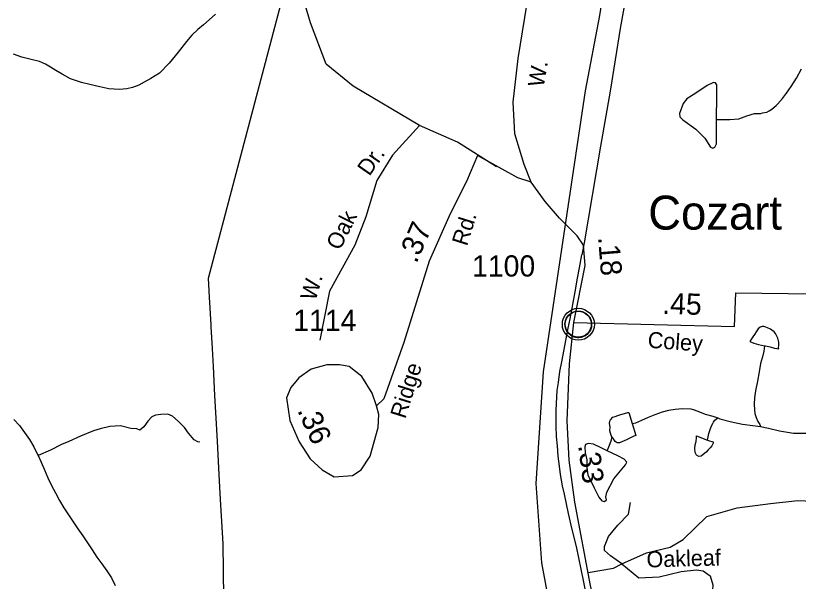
# Model space of a CAD drawing. Extents: x 2056842 to 2160602, y 826753 to 1016856.
# Drawn here: x 2061647 to 2066259, y 853489 to 856821 of the extents above; entities that cross this region are included whole.
import ezdxf

# ---------------------------------------------------------------- set-up
doc = ezdxf.new("R2010")
doc.units = 0
for name, color, linetype in [('Exist Boundary Land Use Reservation Military US Department of Defense', 7, 'Continuous'), ('Exist Boundary Political City Limit New', 7, 'Continuous'), ('Exist Civil Demographics Community CELL', 7, 'Continuous'), ('Exist Civil Demographics Community Label', 7, 'Continuous'), ('Exist Hydrographic Creek Single Shore', 7, 'Continuous'), ('Exist Hydrographic Misc Water Feature', 7, 'Continuous'), ('Exist Railroad Mainline', 7, 'Continuous'), ('Exist Road Non-System Type 51', 7, 'Continuous'), ('Exist Road Non-System Type 51 Label', 7, 'Continuous'), ('Exist Road Secondary Mileage Hundredths English Label', 7, 'Continuous'), ('Exist Road Secondary Type 41 Attributed', 7, 'Continuous'), ('Exist Road Secondary Type 51 Attributed', 7, 'Continuous'), ('Exist Road Secondary Type 51 Label', 7, 'Continuous'), ('Exist Road Secondary Type 51 Number Label', 7, 'Continuous'), ('Map Preparation Boundary City Limit Buffer Line', 7, 'Continuous')]:
    doc.layers.add(name, color=color, linetype=linetype)

msp = doc.modelspace()

# ---------------------------------------------------------------- linework, layer by layer
at = {"layer": 'Exist Boundary Land Use Reservation Military US Department of Defense'}
msp.add_lwpolyline([(2066174.9, 861104.2), (2065853.1, 860720.1), (2065640.8, 860375.6), (2065493.3, 859741.1), (2065336, 858409.3), (2065087.8, 856821.5), (2065002.7, 856377.5), (2064755.9, 854722.1), (2064712.1, 854064.9), (2064745.7, 853597), (2064847.7, 853049), (2064892.2, 852688.1), (2064867, 852393.5), (2064779.9, 852040.8), (2064686.1, 851837.6), (2064419.3, 851474.7), (2064046, 851187.2), (2063767.2, 850891.2), (2063676.8, 850746.1), (2063576.4, 850501.5), (2063457.1, 850039.1), (2063355.1, 849757.2), (2063118.8, 849274.6)], dxfattribs=at)
at = {"layer": 'Exist Boundary Political City Limit New'}
msp.add_lwpolyline([(2062879, 852914.1), (2062869.1, 853709.2), (2062856.4, 853940.2), (2062852.9, 854005.3), (2062844.6, 854155.2), (2062835.9, 854315.1), (2062826.6, 854483.7), (2062821.2, 854582.9), (2062811.9, 854754.9), (2062806, 854860.4), (2062799, 854988.2), (2062798.4, 855000), (2062789.5, 855162.2), (2062783.2, 855275.6), (2063229.1, 856963.7)], dxfattribs=at)
at = {"layer": 'Exist Civil Demographics Community CELL'}
msp.add_lwpolyline([(2064884.9, 855015.5), (2064885.9, 855021.1), (2064887.6, 855027.7), (2064890.6, 855034.9), (2064893.5, 855040.6), (2064896.8, 855046.4), (2064900.6, 855051.5), (2064904.6, 855055.8), (2064909.1, 855060.4), (2064914.7, 855065), (2064920.1, 855068.7), (2064925, 855071.6), (2064930, 855074), (2064935.5, 855076.3), (2064941.1, 855078.1), (2064945.5, 855079.3), (2064950.3, 855080), (2064954.4, 855080.7), (2064960.8, 855081), (2064965.2, 855080.9), (2064970.9, 855080.6), (2064975.8, 855079.9), (2064980.7, 855078.9), (2064985.7, 855077.5), (2064990.9, 855075.6), (2064997.5, 855072.7), (2065003.8, 855069.2), (2065008.9, 855065.6), (2065014, 855061.6), (2065017.3, 855058.5), (2065021.5, 855054.1), (2065025.3, 855049.4), (2065028.4, 855044.8), (2065031.5, 855039.8), (2065034, 855034.6), (2065036, 855029.6), (2065037.6, 855024.6), (2065038.9, 855020), (2065040, 855014), (2065040.6, 855009.3), (2065040.8, 855003.3), (2065040.7, 854997.5), (2065040.1, 854991.8), (2065039.1, 854986.3), (2065037.5, 854980.1), (2065035.6, 854974.3), (2065033.3, 854969.2), (2065030.2, 854963.2), (2065026.9, 854957.9), (2065023.4, 854953.2), (2065019.2, 854948.5), (2065013.9, 854943.5), (2065008.9, 854939.4), (2065003.9, 854935.9), (2064999.6, 854933.4), (2064992.8, 854930.2), (2064985.6, 854927.5), (2064979.7, 854926), (2064973.1, 854924.7), (2064968.6, 854924.3), (2064964.1, 854924), (2064958.6, 854924), (2064954.3, 854924.4), (2064948.6, 854925.1), (2064942.7, 854926.4), (2064938.1, 854927.8), (2064933, 854929.6), (2064928.4, 854931.6), (2064924.5, 854933.9), (2064917.6, 854937.9), (2064912.1, 854942.2), (2064907.2, 854946.7), (2064902.7, 854951.5), (2064899.5, 854955.5), (2064896.5, 854959.7), (2064892.4, 854966.8), (2064890.7, 854970.3), (2064889, 854974.3), (2064886.4, 854982.5), (2064884.9, 854989.6), (2064884.2, 854994.7), (2064883.9, 855001.1), (2064883.8, 855005.8), (2064884.4, 855012.2)], close=True, dxfattribs=at)
for centre, radius in [((2064962.5, 855003.1), 94.3), ((2064962.2, 855003.4), 76.7)]:
    msp.add_circle(centre, radius, dxfattribs=at)
at = {"layer": 'Exist Hydrographic Creek Single Shore'}
for points in [[(2062825.2, 856829.5), (2062787, 856797.5), (2062753.2, 856767.3), (2062720.8, 856739.3), (2062685.1, 856705.5), (2062653.1, 856669.3), (2062605.4, 856607.1), (2062551.4, 856541.1), (2062493.8, 856482.9), (2062443.8, 856451.1), (2062404, 856428.7), (2062373.7, 856412.6), (2062335.5, 856398.5), (2062301.5, 856390.7), (2062258, 856386.7), (2062195.7, 856390.5), (2062143.8, 856402.5), (2062083.7, 856416.5), (2062035.9, 856428.2), (2061969.7, 856450), (2061921.9, 856475.9), (2061883.4, 856497.9), (2061851.4, 856517.8), (2061823.5, 856535.9), (2061787.4, 856551.9), (2061737.6, 856563.5), (2061683.5, 856577.4), (2061633.4, 856593.5)], [(2066036.7, 854399.9), (2066083.1, 854391.7), (2066147, 854375.9), (2066231.1, 854362), (2066315.2, 854362.2), (2066402.9, 854368.4), (2066469.2, 854380.6), (2066563.1, 854400.9), (2066664.8, 854424.8), (2066740.7, 854447), (2066776.7, 854459), (2066880.9, 854505.2), (2066950.6, 854541.3), (2067054.4, 854595.8), (2067088.2, 854607.7)], [(2065279.3, 854418.3), (2065301, 854422.2), (2065336.9, 854438.3), (2065376.9, 854456.6), (2065414.8, 854472.4), (2065458.9, 854486.8), (2065495, 854496.7), (2065532.9, 854502.7), (2065577, 854507), (2065624.6, 854505.1), (2065644.9, 854499.1), (2065676.8, 854487), (2065709, 854473.2), (2065755, 854461.4), (2065784.9, 854451.2)], [(2061636.7, 854442.5), (2061669.7, 854405.8), (2061699.9, 854366), (2061727.7, 854324), (2061753.4, 854280.8), (2061776.6, 854236.7), (2061779, 854231)], [(2062731.9, 854307.6), (2062719.8, 854311.5), (2062699.3, 854321.5), (2062665.7, 854361.5), (2062641.1, 854395.6), (2062605.4, 854431.5), (2062571.3, 854461.4), (2062543, 854473.4), (2062503.3, 854471.3), (2062471.1, 854467.3), (2062449.5, 854457.2), (2062425.5, 854433.2), (2062403.2, 854398.9), (2062379.4, 854378.9), (2062361.8, 854386.9), (2062325.5, 854388.7), (2062265.2, 854404.8), (2062201.2, 854400.7), (2062145.2, 854386.4), (2062105.5, 854374.6), (2062029.6, 854344.4), (2061959.7, 854312.3), (2061917.4, 854294), (2061851.8, 854262.2), (2061779, 854231)], [(2061779, 854231), (2061797.1, 854191.4), (2061816.5, 854145), (2061836.4, 854098.9), (2061858.4, 854054.2), (2061881.1, 854009.8), (2061905.7, 853965.9), (2061930.8, 853922.7), (2061957.8, 853880.5), (2061985.7, 853839.3), (2062014.2, 853798.1), (2062042.5, 853756.9), (2062070, 853715), (2062097.5, 853673.4), (2062124.9, 853631.6), (2062154.9, 853591.3), (2062184.6, 853551.1), (2062211.7, 853509.3), (2062232.6, 853464.3)]]:
    msp.add_lwpolyline(points, dxfattribs=at)
at = {"layer": 'Exist Hydrographic Misc Water Feature'}
for points in [[(2065776.7, 856208.6), (2065854.8, 856209.9), (2065908, 856214.3), (2065954.6, 856230.3), (2066000.1, 856245.1), (2066037.3, 856245.6), (2066047.6, 856247.8), (2066073.6, 856253.6), (2066087.4, 856259.6), (2066103.6, 856269.7), (2066127.6, 856291.6), (2066135.8, 856299.7), (2066165.5, 856333.7), (2066189.3, 856363.8), (2066217.2, 856403.8), (2066247.3, 856452), (2066277, 856507.9)], [(2065776.7, 856208.6), (2065778.8, 856348.7), (2065778.8, 856414), (2065769.8, 856425.6), (2065759.6, 856426.8), (2065722.5, 856408.9), (2065654.7, 856365.4), (2065601, 856330.8), (2065580.5, 856303.9), (2065558.8, 856245.1), (2065560, 856224.6), (2065577.9, 856207.9), (2065654.7, 856152.9), (2065707.1, 856100.4), (2065740.4, 856046.7), (2065754.5, 856041.5), (2065767.3, 856046.7), (2065776.2, 856067.1), (2065776.7, 856208.6)], [(2066059.9, 854875.6), (2066065.8, 854875.9), (2066092.1, 854869.9), (2066117.9, 854862), (2066132.1, 854859.8), (2066144.2, 854858), (2066142.1, 854864), (2066144.4, 854879.9), (2066144, 854897.8), (2066138.2, 854921.8), (2066123.9, 854947.9), (2066115.7, 854958), (2066102.1, 854967.8), (2066094.1, 854973.9), (2066077.9, 854981.6), (2066068.1, 854985.6), (2066056, 854989.8), (2066045.7, 854989.8), (2066034, 854985.9), (2066021.7, 854975.6), (2066009.6, 854959.5), (2065999.8, 854943.6), (2065990.4, 854929.6), (2065982.4, 854917.4), (2065972.1, 854901.6), (2065996.3, 854891.8), (2066023.8, 854883.6), (2066059.9, 854875.6)], [(2066059.9, 854875.6), (2066056.4, 854843.7), (2066048, 854811.7), (2066036.3, 854771.7), (2066028.7, 854723.8), (2066018.5, 854667.7), (2066006.6, 854611.5), (2066000.4, 854569.8), (2065998.8, 854531.5), (2066000.6, 854499.6), (2066003.1, 854477.7), (2066010.9, 854453.8), (2066020.9, 854429.5), (2066031.2, 854411.8), (2066036.7, 854399.9)], [(2065161.3, 854338), (2065155.4, 854348.2), (2065148.8, 854376), (2065149.2, 854398.3), (2065147, 854418), (2065148.8, 854432), (2065151.1, 854440.1), (2065165.2, 854456.3), (2065179, 854460.2), (2065195, 854466.4), (2065213, 854472.2), (2065234.8, 854478.2), (2065255.1, 854482.4), (2065259.2, 854484.2), (2065279.3, 854418.3)], [(2065723.2, 854321.3), (2065727.5, 854339.4), (2065730.8, 854359.1), (2065739, 854383), (2065747, 854405.3), (2065754.8, 854419.2), (2065758.7, 854427.1), (2065766.9, 854437.3), (2065784.9, 854451.2)], [(2065784.9, 854451.2), (2065797, 854445.3), (2065864.9, 854429.3), (2065928.9, 854415.5), (2065991, 854407.7), (2066036.7, 854399.9)], [(2065279.3, 854418.3), (2065301.2, 854348.4), (2065289.3, 854344.5), (2065266.9, 854332.5), (2065245.4, 854322.4), (2065205.2, 854304.1), (2065191.3, 854304.2), (2065179, 854312.1), (2065168.9, 854328.3), (2065161.3, 854338)], [(2065133, 854258.3), (2065143.1, 854280.2), (2065149.5, 854300), (2065157.2, 854321.9), (2065159.3, 854334.2), (2065161.3, 854338)], [(2065723.2, 854321.3), (2065735.3, 854317.1), (2065749, 854313.3), (2065757.2, 854311.3), (2065757.2, 854303.2), (2065749.4, 854287.3), (2065739.4, 854275.1), (2065727.1, 854263.1), (2065715.4, 854249.1), (2065697.4, 854235.1), (2065687.1, 854227), (2065673.2, 854225), (2065659.4, 854231.2), (2065651.4, 854247), (2065649.4, 854271.2), (2065651.4, 854292.9), (2065657.4, 854313.1), (2065659.2, 854335.1), (2065659.2, 854345.3), (2065723.2, 854321.3)], [(2065133, 854258.3), (2065097.7, 854275.7), (2065051.6, 854297.5), (2065022.2, 854301.3), (2065005.6, 854294.9), (2065000.5, 854280.8), (2065003, 854246.3), (2065012, 854205.3), (2065013.3, 854159.2), (2065018.4, 854115.7), (2065055.5, 854040.2), (2065083.6, 853985.1), (2065101.5, 853963.4), (2065116.9, 853959.5), (2065128.4, 853968.5), (2065124.6, 853986.4), (2065129.7, 854013.3), (2065171.9, 854092.7), (2065241, 854174.6), (2065247.4, 854189.9), (2065233.3, 854207.9), (2065194.9, 854228.3), (2065133, 854258.3)]]:
    msp.add_lwpolyline(points, dxfattribs=at)
at = {"layer": 'Exist Railroad Mainline'}
for points in [[(2065300.5, 857259.5), (2065209.9, 856745.3), (2065150.3, 856376.5), (2065093.6, 856051.6), (2064995.9, 855483.5), (2064982.4, 855411.8)], [(2065021.9, 853346.7), (2064992.9, 853493.3), (2064951.1, 853694.2), (2064927.1, 853794.7), (2064905.1, 853889.2), (2064881.4, 854001.7), (2064868.4, 854052), (2064857.8, 854118.2), (2064850.8, 854166.4), (2064844, 854226.5), (2064839.3, 854286.6), (2064834.4, 854342.7), (2064831.7, 854404.8), (2064832.6, 854448.8), (2064831.5, 854494.8), (2064835.2, 854574.7), (2064838, 854612.7), (2064845, 854660.5), (2064854.3, 854724.4), (2064865.5, 854782.1), (2064903.5, 854979.4), (2064914.7, 855035.1), (2064930.4, 855118.8), (2064944, 855194.6), (2064957.6, 855274.3), (2064968.9, 855336.1), (2064982.4, 855411.8)]]:
    msp.add_lwpolyline(points, dxfattribs=at)
at = {"layer": 'Exist Road Non-System Type 51'}
for points in [[(2064026.4, 856174.8), (2063635.4, 856405.6), (2063477.2, 856535.9), (2063384.1, 856778.1), (2063272.4, 857159.9), (2063281.7, 857532.4), (2063337.6, 858519.6), (2063356.2, 859022.5), (2063356.2, 859255.3), (2063179.4, 859538.4), (2063002.5, 859780.6), (2062723.3, 860022.7), (2062481.4, 860143.8), (2062323.2, 860320.7), (2062164.9, 860749.1), (2061988.1, 861214.8)], [(2064026.4, 856174.8), (2063868, 855999.5), (2063775, 855850.5), (2063709.8, 855636.3), (2063644.7, 855468.7), (2063495.8, 855198.6), (2063439.9, 854909.9)], [(2064480.6, 855931.1), (2064250.7, 856075.1), (2064026.4, 856174.8)], [(2065020.3, 853541.1), (2065169, 853565.9), (2065219.3, 853592.5), (2065364.1, 853657.5), (2065503, 853690.1), (2065579.8, 853734.4), (2065718.7, 853870.5), (2065899, 853920.8), (2066094.1, 853947.4), (2066256.6, 853965.1), (2066428, 853956.2), (2066640.8, 853926.7), (2066829.9, 853894.1), (2066897.9, 853846.8), (2066939.3, 853737.4), (2066948.1, 853645.7), (2067019.1, 853601.4), (2067169.8, 853660.5)], [(2065219.3, 853592.5), (2065151.3, 853639.8), (2065115.8, 853669.4), (2065115.8, 853693), (2065139.5, 853752.2), (2065195.6, 853820.2), (2065257.7, 853885.3), (2065269.5, 853953.3)], [(2065219.3, 853592.5), (2065319.8, 853509.1), (2065438, 853515), (2065568, 853547.5), (2065659.6, 853556.4), (2065698, 853550.5), (2065739.4, 853520.9), (2065754.2, 853467.7), (2065751.2, 853405.6), (2065703.9, 853376), (2065541.4, 853331.6), (2065349.3, 853310.9)]]:
    msp.add_lwpolyline(points, dxfattribs=at)
at = {"layer": 'Exist Road Secondary Type 41 Attributed'}
for points in [[(2063773.4, 854522.9), (2063748.5, 854596.7), (2063686.1, 854695.4), (2063612.4, 854753.6), (2063554.3, 854765.1), (2063480.5, 854765.1), (2063387.6, 854739.6), (2063315.9, 854686.6), (2063268.2, 854630.5), (2063242.2, 854570.2)], [(2063242.2, 854570.2), (2063263.5, 854435.6), (2063318.5, 854310.9), (2063381.9, 854211.2), (2063453.5, 854144.7), (2063524.7, 854103.6), (2063631, 854112)], [(2063631, 854112), (2063683.6, 854145.2), (2063736, 854225.7), (2063783.8, 854395.1), (2063786.9, 854472), (2063773.4, 854522.9)]]:
    msp.add_lwpolyline(points, dxfattribs=at)
at = {"layer": 'Exist Road Secondary Type 51 Attributed'}
for points in [[(2064684.1, 855839.6), (2064643.1, 855944), (2064589.1, 856124.9), (2064578.7, 856311.9), (2064608.8, 856568.6), (2064801, 857754.3), (2065030.5, 859012.8), (2065226.7, 860248.4), (2065364.9, 861035.1), (2065425.1, 861317.8), (2065553.9, 861629.5), (2065725.2, 861986), (2065930.8, 862276.9), (2066130.2, 862526.4), (2066317.1, 862696.8), (2066825, 863107.3), (2067775.2, 863846.1), (2068132.4, 864147.5), (2068556.1, 864440.6), (2069020.3, 864778.3), (2069626.8, 865266.7), (2069800.3, 865437.4)], [(2064684.1, 855839.6), (2064605.2, 855866.6), (2064367.5, 855997.1), (2064304.2, 855845.2), (2064206.4, 855654.6), (2064083.9, 855374), (2063933.3, 854895), (2063817, 854564.5), (2063773.4, 854522.9)], [(2064936.5, 855014.5), (2065002.5, 855349.8), (2064992.8, 855468.3), (2064956.2, 855524.7), (2064852.4, 855628.6), (2064767.2, 855726.3), (2064684.1, 855839.6)], [(2064936.5, 855014.5), (2065883.4, 854990.6), (2065889.7, 855188.1), (2067122.6, 855172.5)], [(2066976.4, 849302.5), (2066827.4, 849529.6), (2066583.4, 849954.6), (2066340.4, 850362), (2066245.9, 850589.6), (2066191.9, 850780.8), (2066158.6, 851005.3), (2066128.5, 851176.7), (2066064.1, 851299.4), (2065906.3, 851503), (2065491.9, 851988.3), (2065329.9, 852210.7), (2065215.7, 852418.6), (2065151.3, 852589), (2065154.4, 852718.9), (2065131.6, 852966.2), (2065106.6, 853138.7), (2065035, 853464), (2064941.5, 853954.5), (2064909.3, 854202.9), (2064896.9, 854433.6), (2064911.4, 854770.3), (2064936.5, 855014.5)]]:
    msp.add_lwpolyline(points, dxfattribs=at)
at = {"layer": 'Map Preparation Boundary City Limit Buffer Line'}
msp.add_lwpolyline([(2062879, 852914.1), (2062869.1, 853709.2), (2062856.4, 853940.2), (2062852.9, 854005.3), (2062844.6, 854155.2), (2062835.9, 854315.1), (2062826.6, 854483.7), (2062821.2, 854582.9), (2062811.9, 854754.9), (2062806, 854860.4), (2062799, 854988.2), (2062798.4, 855000), (2062789.5, 855162.2), (2062783.2, 855275.6), (2063229.1, 856963.7)], dxfattribs=at)

# ---------------------------------------------------------------- texts
at = {"layer": 'Exist Civil Demographics Community Label'}
msp.add_text('Cozart', height=200, dxfattribs=at).set_placement((2065374.5, 855560.8))
at = {"layer": 'Exist Road Non-System Type 51 Label'}
for s, rotation, p in [('Dr.', 55.1089, (2063731.2, 855871.4)), ('Oak', 63.3464, (2063556.9, 855433.3)), ('W.', 73.3127, (2063413.6, 855136.7)), ('Oakleaf', 1.5937, (2065365.4, 853570.1))]:
    msp.add_text(s, height=95, rotation=rotation, dxfattribs=at).set_placement(p)
at = {"layer": 'Exist Road Secondary Mileage Hundredths English Label'}
for s, rotation, p in [('.37', 66.4075, (2064008.2, 855357)), ('.18', 274.69, (2065078.2, 855516)), ('.45', 358.5562, (2065455.8, 855063.9)), ('.36', 293.8149, (2063305, 854496.4)), ('.33', 277.3854, (2064961.1, 854289.4))]:
    msp.add_text(s, height=125, rotation=rotation, dxfattribs=at).set_placement(p)
at = {"layer": 'Exist Road Secondary Type 51 Label'}
for s, rotation, p in [('W.', 80.3897, (2064758, 856395.9)), ('Rd.', 72.5257, (2064305.8, 855459.5)), ('Coley', 355.8198, (2065368.7, 854865.3)), ('Ridge', 72.5257, (2063942.6, 854442))]:
    msp.add_text(s, height=95, rotation=rotation, dxfattribs=at).set_placement(p)
at = {"layer": 'Exist Road Secondary Type 51 Number Label'}
for s, p in [('1100', (2064336.3, 855284.3)), ('1114', (2063282.9, 854963.5))]:
    msp.add_text(s, height=125, dxfattribs=at).set_placement(p)

doc.saveas('drawing.dxf')
